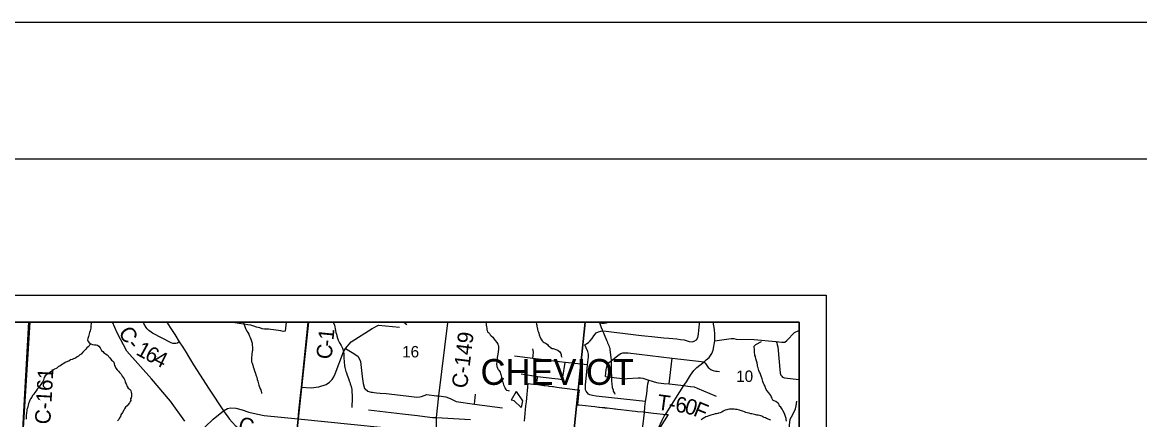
# Model space of a CAD drawing. Extents: x 0 to 34, y 0 to 22.
# Drawn here: x 6.05 to 10.15, y 20.543 to 22 of the extents above; entities that cross this region are included whole.
import ezdxf

# ---------------------------------------------------------------- set-up
doc = ezdxf.new("R2010")
doc.units = 0
for name, color, linetype in [('GM_X_City_Street', 7, 'Continuous'), ('GM_X_Corporation', 7, 'Continuous'), ('GM_X_Corporation_Text', 7, 'Continuous'), ('GM_X_County_Road', 7, 'Continuous'), ('GM_X_County_Road_Text', 7, 'Continuous'), ('GM_X_Minor_Lake', 7, 'Continuous'), ('GM_X_Minor_River', 7, 'Continuous'), ('GM_X_Rail_Line', 7, 'Continuous'), ('GM_X_Section_Text', 7, 'Continuous'), ('GM_X_Township_Road', 7, 'Continuous'), ('GM_X_Township_Road_Text', 7, 'Continuous'), ('SH_Border', 7, 'Continuous'), ('SH_Cut_Line', 7, 'Continuous'), ('SH_Data', 7, 'Continuous')]:
    doc.layers.add(name, color=color, linetype=linetype)

msp = doc.modelspace()

# ---------------------------------------------------------------- linework, layer by layer
at = {"layer": 'GM_X_City_Street'}
msp.add_line((8.3245, 20.4975), (8.3324, 20.5696), dxfattribs=at)
at = {"layer": 'GM_X_Corporation'}
for points in [[(8.9, 14.3814), (8.9, 20.9), (2.1, 20.9)], [(8.9, 17.1766), (8.9, 20.9), (4.0645, 20.9), (4.0111, 20.3696), (4.0006, 20.2658), (3.9936, 20.1954), (3.918, 19.4442), (3.8667, 18.9339), (3.8234, 18.553), (3.8126, 18.3974), (3.8023, 18.3182), (3.7454, 17.7286)], [(7.8922, 20.5373), (7.8936, 20.5515), (7.895, 20.5656), (7.8965, 20.5797), (7.8979, 20.5938), (7.8993, 20.608), (7.9007, 20.6221), (7.9023, 20.6381), (7.9033, 20.6476), (7.9049, 20.6636), (7.9061, 20.6757), (7.9146, 20.6746), (7.9149, 20.6746), (7.9324, 20.6724), (7.9418, 20.6712), (7.9632, 20.6685), (7.9681, 20.6679), (7.9794, 20.6664), (7.9822, 20.6661), (7.9955, 20.6643), (7.9973, 20.6641), (7.9992, 20.6639), (8.0117, 20.6622), (8.0286, 20.6601), (8.0301, 20.6599), (8.0593, 20.6561), (8.0765, 20.6538), (8.0767, 20.6538), (8.0923, 20.6518), (8.0926, 20.6518), (8.091, 20.6367), (8.0896, 20.6228), (8.0871, 20.5977), (8.0929, 20.597), (8.1169, 20.5944), (8.137, 20.5922), (8.1512, 20.5907), (8.1652, 20.589), (8.1679, 20.5887), (8.1773, 20.5877), (8.1856, 20.5868), (8.1868, 20.5866), (8.1962, 20.5856), (8.2059, 20.5845), (8.215, 20.5835), (8.2245, 20.5825), (8.2262, 20.5823), (8.2338, 20.5815), (8.2466, 20.5801), (8.2669, 20.5779), (8.2872, 20.5756), (8.2997, 20.5742), (8.3075, 20.5733), (8.3279, 20.5712), (8.3373, 20.5702), (8.3656, 20.5672), (8.4137, 20.562), (8.4199, 20.5613), (8.3907, 20.515)]]:
    msp.add_lwpolyline(points, dxfattribs=at)
for points in [[(6.077, 20.9), (5.0731, 20.9), (5.0456, 20.6041), (6.0521, 20.4929)], [(7.0997, 20.9), (6.077, 20.9), (6.0521, 20.4929), (7.0465, 20.3953)], [(8.1157, 20.9), (7.0997, 20.9), (7.0465, 20.3953), (8.0517, 20.2839)], [(8.9, 20.1965), (8.9, 20.9), (8.1157, 20.9), (8.0517, 20.2839)]]:
    msp.add_lwpolyline(points, close=True, dxfattribs=at)
at = {"layer": 'GM_X_County_Road'}
msp.add_line((7.0645, 20.5751), (7.0717, 20.643), dxfattribs=at)
for points in [[(6.0357, 20.3327), (6.0589, 20.3625), (6.0642, 20.3768), (6.0699, 20.4348), (6.0514, 20.507), (6.0739, 20.9)], [(6.6257, 20.828), (6.6192, 20.8239), (6.6133, 20.822), (6.6074, 20.8216), (6.602, 20.8224), (6.5954, 20.825), (6.5275, 20.8599), (6.5219, 20.8635), (6.5138, 20.8692), (6.5074, 20.8765), (6.5043, 20.8807), (6.4958, 20.8952), (6.4931, 20.9)], [(6.5797, 20.9), (6.5922, 20.8807), (6.609, 20.8555), (6.6257, 20.828), (6.6385, 20.8086), (6.6511, 20.7887), (6.6599, 20.7739), (6.6778, 20.7443), (6.7353, 20.6548), (6.7877, 20.5749), (6.8101, 20.5442), (6.8193, 20.533), (6.8328, 20.5185), (6.8419, 20.5096), (6.8623, 20.4912), (6.8749, 20.4813), (6.8851, 20.4742), (6.902, 20.4629), (6.9135, 20.4559), (6.9278, 20.4482), (6.9415, 20.4415), (6.989, 20.4219), (7.0504, 20.3965)], [(7.0717, 20.643), (7.0737, 20.6624), (7.099, 20.9)], [(7.5701, 20.4942), (7.5701, 20.5502), (7.5787, 20.6296), (7.6113, 20.8976), (7.6116, 20.9)], [(8.4122, 20.5655), (8.4775, 20.6676), (8.4871, 20.6816), (8.5023, 20.7057), (8.5143, 20.7232), (8.5254, 20.7338), (8.5521, 20.755), (8.5598, 20.7625), (8.5701, 20.7713), (8.5796, 20.7859), (8.5846, 20.7982), (8.5904, 20.8323), (8.5915, 20.856), (8.5892, 20.874), (8.5848, 20.9)], [(8.5904, 20.8323), (8.6504, 20.8401), (8.6603, 20.8399), (8.6689, 20.8381), (8.7354, 20.8374), (8.8148, 20.8292), (8.818, 20.824), (8.8202, 20.8175), (8.8217, 20.8096), (8.8313, 20.7127), (8.8333, 20.706), (8.8363, 20.7017), (8.8398, 20.6986), (8.847, 20.6963), (8.9, 20.6906)], [(6.7877, 20.5749), (6.803, 20.5835), (6.8139, 20.5861), (6.8329, 20.5848), (6.857, 20.5786), (6.8813, 20.5698), (6.9073, 20.564), (6.9367, 20.5585), (7.0614, 20.546), (7.5701, 20.4942), (7.7383, 20.4795), (7.8165, 20.4727), (7.8632, 20.4681), (7.8783, 20.4665)], [(7.0504, 20.3965), (7.0614, 20.546), (7.0645, 20.5751)], [(8.3489, 20.3815), (8.3492, 20.3828), (8.3647, 20.4587), (8.3698, 20.4768), (8.3757, 20.4915), (8.3789, 20.4993), (8.3845, 20.5117), (8.3976, 20.5409), (8.4056, 20.5553), (8.4122, 20.5655)]]:
    msp.add_lwpolyline(points, dxfattribs=at)
at = {"layer": 'GM_X_Minor_Lake'}
for points in [[(7.8623, 20.6457), (7.8855, 20.6121), (7.8808, 20.5872), (7.8551, 20.6117), (7.8441, 20.6142)], [(7.8623, 20.6457), (7.8441, 20.6142)]]:
    msp.add_lwpolyline(points, dxfattribs=at)
at = {"layer": 'GM_X_Minor_River'}
msp.add_line((7.4498, 20.9), (7.4609, 20.8916), dxfattribs=at)
for points in [[(6.3032, 20.9), (6.3019, 20.8953), (6.3013, 20.8884), (6.3015, 20.8831), (6.3013, 20.8786), (6.3004, 20.874), (6.2983, 20.8684), (6.2958, 20.862), (6.2949, 20.8575), (6.2932, 20.8526), (6.2919, 20.8477), (6.2902, 20.841), (6.2892, 20.836), (6.2913, 20.8291), (6.296, 20.8233), (6.3012, 20.8208), (6.3072, 20.8183), (6.3148, 20.8177), (6.3209, 20.8171), (6.3261, 20.8158), (6.3309, 20.8122), (6.3353, 20.8067), (6.3378, 20.8009), (6.3399, 20.7963), (6.3447, 20.7923), (6.3494, 20.7872), (6.355, 20.7844), (6.361, 20.78), (6.3705, 20.7698), (6.3767, 20.7616), (6.3811, 20.7588), (6.3851, 20.7533), (6.3868, 20.7472), (6.3881, 20.7418), (6.3899, 20.7372), (6.3927, 20.7318), (6.3978, 20.7251), (6.4022, 20.7204), (6.4062, 20.7157), (6.4121, 20.7094), (6.4164, 20.7024), (6.4229, 20.6927), (6.4254, 20.6881), (6.4274, 20.6804), (6.431, 20.6746), (6.4344, 20.6638), (6.4376, 20.6584), (6.445, 20.6532), (6.4475, 20.6485), (6.4485, 20.6439), (6.4502, 20.6378), (6.4504, 20.6332), (6.4503, 20.6287), (6.4493, 20.6234), (6.4469, 20.6189), (6.4479, 20.6136), (6.445, 20.6091), (6.4434, 20.6042), (6.4382, 20.5987), (6.4339, 20.5939), (6.4284, 20.5884)], [(6.8604, 20.9), (6.8623, 20.8953), (6.8647, 20.8876), (6.8689, 20.8775), (6.8739, 20.8675), (6.8775, 20.862), (6.8803, 20.8566), (6.8839, 20.8493), (6.886, 20.8439), (6.8877, 20.8381), (6.8901, 20.8312), (6.8925, 20.8235), (6.8934, 20.817), (6.8942, 20.8071), (6.8944, 20.8026), (6.8942, 20.7969), (6.8933, 20.7923), (6.8923, 20.7844), (6.8913, 20.7776), (6.8903, 20.7727), (6.8902, 20.7681), (6.8912, 20.7544), (6.8926, 20.7494), (6.8954, 20.7432), (6.8971, 20.7371), (6.8995, 20.7306), (6.9019, 20.7217), (6.9047, 20.7163), (6.9081, 20.7037), (6.9102, 20.6986), (6.9118, 20.6898), (6.9135, 20.6845), (6.9179, 20.6687), (6.922, 20.6564), (6.9245, 20.6518), (6.9268, 20.6411), (6.9278, 20.6385)], [(7.1914, 20.9), (7.1919, 20.8983), (7.1947, 20.8898), (7.1964, 20.8829), (7.1976, 20.8757), (7.1989, 20.8699), (7.2006, 20.863), (7.2023, 20.8569), (7.2039, 20.85), (7.2063, 20.8419), (7.2087, 20.8346), (7.2109, 20.83), (7.2137, 20.8242), (7.2194, 20.8149), (7.2227, 20.8094), (7.2248, 20.8048), (7.2272, 20.7975), (7.2285, 20.7917), (7.2294, 20.783), (7.2295, 20.7754), (7.2297, 20.77), (7.2303, 20.7548), (7.2317, 20.7403), (7.2337, 20.7342), (7.2366, 20.7193), (7.2395, 20.7146), (7.2419, 20.7054), (7.2447, 20.7004), (7.2464, 20.6935), (7.2491, 20.6854), (7.2513, 20.6804), (7.2533, 20.6738), (7.2564, 20.6642), (7.2583, 20.6531), (7.2589, 20.6482), (7.2594, 20.6421), (7.2595, 20.6341), (7.2599, 20.6223), (7.26, 20.6139), (7.2594, 20.5965), (7.2585, 20.5879)], [(7.751, 20.9), (7.751, 20.8994), (7.7516, 20.894), (7.7519, 20.8891), (7.7529, 20.8837), (7.7539, 20.878), (7.7545, 20.8726), (7.7551, 20.8695), (7.7569, 20.8649), (7.761, 20.8621), (7.7636, 20.8586), (7.7669, 20.854), (7.7698, 20.8505), (7.7762, 20.845), (7.7787, 20.8418), (7.7817, 20.838), (7.785, 20.8329), (7.7909, 20.8263), (7.7941, 20.8201), (7.7959, 20.817), (7.7969, 20.8113), (7.7967, 20.8017), (7.7943, 20.7832), (7.7933, 20.7763), (7.7924, 20.7706), (7.7917, 20.7589), (7.7908, 20.7524), (7.7902, 20.7471), (7.7911, 20.7383), (7.7918, 20.7349), (7.7929, 20.7314), (7.7954, 20.7271), (7.7984, 20.724), (7.8006, 20.7205), (7.8027, 20.7167), (7.8045, 20.712), (7.8056, 20.709), (7.8066, 20.704), (7.8079, 20.6986), (7.8093, 20.691), (7.8103, 20.6879), (7.8117, 20.6833), (7.8124, 20.6798), (7.8138, 20.6752), (7.8159, 20.6702), (7.8177, 20.6656), (7.8202, 20.6613), (7.822, 20.6571), (7.8235, 20.654), (7.8264, 20.6513), (7.8328, 20.6492), (7.8359, 20.6487)], [(7.9349, 20.9), (7.9354, 20.898), (7.9364, 20.893), (7.9375, 20.8892), (7.9381, 20.885), (7.9388, 20.8819), (7.9404, 20.8731), (7.9418, 20.8689), (7.9436, 20.8639), (7.9446, 20.8597), (7.9468, 20.8539), (7.9478, 20.8508), (7.9489, 20.8474), (7.9521, 20.8397), (7.9543, 20.8354), (7.9568, 20.8323), (7.9609, 20.8284), (7.965, 20.8264), (7.9721, 20.822), (7.9766, 20.8184), (7.9799, 20.8153), (7.9855, 20.8102), (7.9885, 20.8078), (7.9937, 20.8042), (7.9979, 20.8034), (8.0017, 20.8025), (8.0073, 20.8), (8.0111, 20.7988), (8.0144, 20.7972), (8.0219, 20.7916), (8.0259, 20.7854), (8.0273, 20.7812), (8.0276, 20.7766), (8.0293, 20.7716)], [(8.1633, 20.9), (8.1682, 20.8987), (8.1712, 20.8975), (8.1761, 20.8966), (8.1795, 20.8965), (8.1845, 20.8968), (8.1894, 20.8974), (8.1929, 20.8984), (8.1963, 20.8995), (8.1976, 20.9)], [(8.1674, 20.8989), (8.1748, 20.8776), (8.177, 20.8745), (8.1777, 20.8711), (8.1824, 20.8618), (8.1852, 20.8556), (8.1877, 20.8491), (8.1909, 20.841), (8.1934, 20.8348), (8.1956, 20.829), (8.1977, 20.8244), (8.1991, 20.8202), (8.2016, 20.8148), (8.2034, 20.8102), (8.2052, 20.8048), (8.2061, 20.7987), (8.2074, 20.7906), (8.2087, 20.7799), (8.2092, 20.7704), (8.2101, 20.7609), (8.2102, 20.751), (8.2107, 20.7407), (8.2108, 20.7327), (8.211, 20.7266), (8.2109, 20.7212), (8.2111, 20.7132), (8.2116, 20.706), (8.2119, 20.701), (8.2123, 20.6881), (8.2121, 20.6812), (8.2127, 20.6763), (8.2126, 20.6724), (8.2139, 20.6637), (8.2146, 20.6606), (8.2174, 20.6517), (8.2184, 20.6475), (8.2224, 20.6398), (8.2242, 20.6359)], [(8.8245, 20.6016), (8.8204, 20.6048), (8.8144, 20.6099), (8.8084, 20.612), (8.8035, 20.6148), (8.801, 20.6194), (8.8004, 20.6236), (8.7982, 20.6275), (8.796, 20.6318), (8.7887, 20.6415), (8.7835, 20.6489), (8.7799, 20.6539), (8.777, 20.6593), (8.7752, 20.6651), (8.772, 20.6709), (8.7688, 20.6786), (8.767, 20.6828), (8.7659, 20.6871), (8.7646, 20.692), (8.7614, 20.7017), (8.76, 20.7063), (8.7568, 20.7132), (8.7553, 20.7171), (8.7528, 20.7232), (8.7507, 20.7275), (8.7497, 20.7328), (8.749, 20.7359), (8.748, 20.7397), (8.7473, 20.7428), (8.7464, 20.7508), (8.7435, 20.7589), (8.7418, 20.7662), (8.7398, 20.7742), (8.7384, 20.7777), (8.7377, 20.7834), (8.7371, 20.788), (8.7368, 20.7918), (8.7362, 20.7979), (8.736, 20.8029), (8.7357, 20.8075), (8.7355, 20.8124), (8.741, 20.818), (8.7618, 20.8296)], [(6.3005, 20.8212), (6.2914, 20.8101), (6.2859, 20.8058), (6.2823, 20.8009), (6.278, 20.7961), (6.2721, 20.7903), (6.265, 20.7829), (6.2604, 20.7804), (6.256, 20.776), (6.2514, 20.7727), (6.2452, 20.7688), (6.2371, 20.7653), (6.2325, 20.7639), (6.2267, 20.7618), (6.2201, 20.7579), (6.2155, 20.7561), (6.2074, 20.7522), (6.2023, 20.7486), (6.1969, 20.7458), (6.1919, 20.7429), (6.1872, 20.7392), (6.1818, 20.7372), (6.1759, 20.7317), (6.1647, 20.7263), (6.16, 20.7223), (6.1546, 20.7183), (6.1491, 20.7151), (6.1433, 20.7115), (6.1382, 20.7067), (6.1332, 20.7031), (6.1299, 20.6975), (6.1283, 20.693), (6.127, 20.6881), (6.1245, 20.6821), (6.1213, 20.6773), (6.118, 20.6713), (6.1137, 20.6669), (6.1104, 20.661), (6.1041, 20.6543), (6.1009, 20.6491), (6.0958, 20.6421), (6.0914, 20.6362), (6.087, 20.6314), (6.0846, 20.6257), (6.0798, 20.6187), (6.0769, 20.6138), (6.0748, 20.6067), (6.0727, 20.6018), (6.0714, 20.5962), (6.0697, 20.5913), (6.0683, 20.5849), (6.0667, 20.5804), (6.0661, 20.5758), (6.065, 20.566), (6.064, 20.5592), (6.0637, 20.5493), (6.0632, 20.5448)], [(6.4284, 20.5884), (6.424, 20.5825), (6.4219, 20.5772), (6.4171, 20.5694), (6.4115, 20.5605), (6.4094, 20.5548), (6.4065, 20.5489), (6.4033, 20.5433), (6.3989, 20.5381)], [(8.8543, 20.5368), (8.8533, 20.5433), (8.8523, 20.5475), (8.8492, 20.5579), (8.8467, 20.5652), (8.8405, 20.5761), (8.8376, 20.5815), (8.8329, 20.5885), (8.8288, 20.5928), (8.827, 20.5966), (8.8245, 20.6016)], [(8.7959, 20.5415), (8.7872, 20.544), (8.7842, 20.5453), (8.7808, 20.5469), (8.777, 20.5493), (8.7725, 20.5513), (8.7673, 20.5534), (8.7639, 20.555), (8.7598, 20.5566), (8.7552, 20.5575), (8.7503, 20.5588), (8.7446, 20.5597), (8.7416, 20.5605), (8.7367, 20.5618), (8.7314, 20.5624), (8.7265, 20.5636), (8.7227, 20.5645), (8.7171, 20.5666), (8.7099, 20.5679), (8.7053, 20.5696), (8.6993, 20.572), (8.6933, 20.5737), (8.6891, 20.575), (8.6854, 20.5766), (8.6812, 20.5782), (8.6725, 20.5796), (8.6672, 20.5801), (8.6615, 20.5811), (8.6532, 20.5817), (8.6482, 20.5814), (8.6444, 20.5808), (8.6383, 20.5798), (8.6345, 20.5788), (8.6295, 20.577), (8.6218, 20.5734), (8.6164, 20.5701), (8.6106, 20.5676), (8.6049, 20.5663), (8.6018, 20.5656), (8.5976, 20.5646), (8.5926, 20.5636), (8.5861, 20.5618), (8.5815, 20.5608), (8.5758, 20.5587), (8.5693, 20.5574), (8.5623, 20.5541), (8.5581, 20.5531), (8.5542, 20.5506), (8.5481, 20.5469), (8.5442, 20.544), (8.5411, 20.5422)]]:
    msp.add_lwpolyline(points, dxfattribs=at)
at = {"layer": 'GM_X_Rail_Line'}
msp.add_lwpolyline([(6.6457, 20.5375), (6.5931, 20.6104), (6.5238, 20.6921), (6.4336, 20.7945), (6.3973, 20.8617), (6.38, 20.9)], dxfattribs=at)
at = {"layer": 'GM_X_Township_Road'}
for p, q in [((7.6113, 20.8976), (7.5882, 20.9)), ((8.4229, 20.6741), (8.4344, 20.7687)), ((7.9386, 20.6829), (7.9401, 20.7012)), ((7.7091, 20.5999), (7.713, 20.6363)), ((8.3364, 20.6096), (8.166, 20.6282)), ((8.3324, 20.5696), (8.3344, 20.5896))]:
    msp.add_line(p, q, dxfattribs=at)
for points in [[(7.0181, 20.9), (7.0145, 20.8678), (7.0073, 20.8664), (6.9979, 20.8684), (6.9535, 20.8742), (6.9385, 20.8751), (6.9298, 20.8763), (6.9212, 20.879), (6.9095, 20.8817), (6.8996, 20.8856), (6.8888, 20.8889), (6.8771, 20.8907), (6.8615, 20.8928), (6.813, 20.9)], [(7.0737, 20.6624), (7.1098, 20.6596), (7.1383, 20.6636), (7.1641, 20.672), (7.1764, 20.6798), (7.1872, 20.6906), (7.1923, 20.7002), (7.1979, 20.7113), (7.2287, 20.791), (7.2361, 20.8038), (7.257, 20.8279), (7.3338, 20.8777), (7.3572, 20.8897), (7.4342, 20.8824)], [(8.3214, 20.8519), (8.3344, 20.8506), (8.3592, 20.8478), (8.3816, 20.8455), (8.4036, 20.8434), (8.4217, 20.8419), (8.4516, 20.8388), (8.4646, 20.8373), (8.4788, 20.8352), (8.4972, 20.8291), (8.508, 20.8283), (8.5155, 20.8301), (8.5232, 20.835), (8.5289, 20.8437), (8.5312, 20.8566), (8.5322, 20.8712), (8.5335, 20.8822), (8.5342, 20.8938), (8.5353, 20.9)], [(8.8148, 20.8292), (8.8372, 20.827), (8.8479, 20.8275), (8.8558, 20.8335), (8.8837, 20.8622), (8.8987, 20.8702), (8.9, 20.8706)], [(8.1139, 20.8171), (8.1212, 20.8222), (8.1274, 20.826), (8.1328, 20.8309), (8.141, 20.841), (8.1467, 20.8504), (8.1521, 20.8569), (8.1561, 20.8609), (8.1637, 20.8648), (8.1729, 20.8673), (8.1824, 20.8682), (8.2915, 20.8553), (8.3103, 20.853), (8.3214, 20.8519)], [(7.2361, 20.8038), (7.266, 20.7859), (7.2816, 20.7742), (7.2909, 20.7563), (7.2963, 20.7008), (7.2999, 20.6753), (7.3059, 20.6573), (7.3082, 20.6554)], [(7.9232, 20.7668), (7.9247, 20.7776), (7.9252, 20.7901), (7.9227, 20.803)], [(8.166, 20.6282), (8.156, 20.6292), (8.1425, 20.6309), (8.1323, 20.6337), (8.1275, 20.6368), (8.1219, 20.642), (8.1191, 20.6469), (8.1169, 20.6517), (8.1161, 20.6585), (8.1166, 20.6694), (8.1238, 20.7433), (8.1272, 20.7732), (8.1269, 20.7833), (8.1245, 20.7927), (8.1192, 20.8065), (8.1139, 20.8171)], [(7.9728, 20.7607), (7.9232, 20.7668), (7.8564, 20.776)], [(7.8798, 20.7108), (7.9401, 20.7012), (8.0039, 20.6943), (8.0157, 20.692), (8.0229, 20.691), (8.0316, 20.6899), (8.0326, 20.6982), (8.0416, 20.7519)], [(8.1238, 20.7433), (8.0416, 20.7519), (7.9797, 20.7598), (7.9728, 20.7607)], [(8.1894, 20.7005), (8.1927, 20.7263), (8.196, 20.7412), (8.1997, 20.7474), (8.2045, 20.7533), (8.2402, 20.7817), (8.2464, 20.7853), (8.2531, 20.7876), (8.2601, 20.7884), (8.273, 20.7873), (8.4344, 20.7687), (8.5521, 20.755)], [(8.5521, 20.755), (8.5546, 20.7515), (8.557, 20.7483), (8.5592, 20.7449), (8.5617, 20.7411), (8.5639, 20.7377), (8.567, 20.7344), (8.5696, 20.7319), (8.5721, 20.7297), (8.576, 20.727), (8.5816, 20.7241), (8.5854, 20.7227), (8.5899, 20.7218), (8.5942, 20.7211), (8.6001, 20.7205), (8.6084, 20.7199)], [(8.1894, 20.7005), (8.2513, 20.6933), (8.2585, 20.6931), (8.2692, 20.6939), (8.3102, 20.6962), (8.3177, 20.696), (8.3262, 20.6949), (8.3372, 20.6919), (8.3491, 20.6878), (8.3767, 20.6796), (8.3847, 20.678), (8.4038, 20.6759), (8.4229, 20.6741), (8.4775, 20.6676)], [(8.3344, 20.5896), (8.3364, 20.6096), (8.3409, 20.6372), (8.3434, 20.6638), (8.3454, 20.6746), (8.3491, 20.6878)], [(8.4775, 20.6676), (8.4922, 20.6659), (8.5023, 20.6646), (8.5149, 20.6631), (8.5256, 20.6587), (8.596, 20.6292)], [(7.3082, 20.6554), (7.3176, 20.6477), (7.3246, 20.6447), (7.3293, 20.6435), (7.3342, 20.6432), (7.3408, 20.6429), (7.3495, 20.6416), (7.3629, 20.6405), (7.3847, 20.6383), (7.4582, 20.6301), (7.4979, 20.6254), (7.5081, 20.6259), (7.5148, 20.6274), (7.5339, 20.6356), (7.5691, 20.6305), (7.5787, 20.6296), (7.6044, 20.6271), (7.6199, 20.6205), (7.6367, 20.6115), (7.642, 20.6095), (7.7091, 20.5999), (7.8123, 20.5867)], [(8.8614, 20.4866), (8.8663, 20.5339), (8.8678, 20.5447), (8.872, 20.5537), (8.8812, 20.5693), (8.8871, 20.5819), (8.8897, 20.5935), (8.8915, 20.6107)], [(6.6912, 20.4885), (6.7499, 20.5442), (6.7877, 20.5749)], [(7.32, 20.5789), (7.4442, 20.5645), (7.5001, 20.5581), (7.5269, 20.554), (7.5549, 20.551), (7.5701, 20.5502), (7.694, 20.5434)]]:
    msp.add_lwpolyline(points, dxfattribs=at)
at = {"layer": 'SH_Border'}
msp.add_lwpolyline([(1.5, 21.5), (33.5, 21.5), (33.5, 0.5), (1.5, 0.5)], close=True, dxfattribs=at)
at = {"layer": 'SH_Cut_Line'}
msp.add_lwpolyline([(0, 0), (34, 0), (34, 22), (0, 22)], close=True, dxfattribs=at)
at = {"layer": 'SH_Data'}
for p, q in [((2, 21), (9, 21)), ((9, 21), (9, 14)), ((2.1, 20.9), (8.9, 20.9)), ((8.9, 20.9), (8.9, 14.1))]:
    msp.add_line(p, q, dxfattribs=at)

# ---------------------------------------------------------------- texts
at = {"layer": 'GM_X_Corporation_Text'}
msp.add_text('CHEVIOT', height=0.0947, rotation=0, dxfattribs=at).set_placement((7.7313, 20.6704))
at = {"layer": 'GM_X_County_Road_Text'}
for s, height, rotation, p in [('C', 0.0568, 300.6958, (6.4006, 20.8639)), ('1', 0.0568, 84.3611, (7.1914, 20.8324)), ('-', 0.0568, 84.1355, (7.189, 20.809)), ('C-149', 0.05682, 83.0806, (7.6815, 20.6558)), ('-', 0.0568, 310.9021, (6.4309, 20.8148)), ('1', 0.0568, 331.2505, (6.4632, 20.7834)), ('6', 0.0568, 332.5993, (6.4952, 20.7659)), ('4', 0.0568, 333.6344, (6.5272, 20.7492)), ('C', 0.0568, 84.0873, (7.1842, 20.7625)), ('C-161', 0.05682, 86.6984, (6.1521, 20.5245)), ('C', 0.0568, 343.9721, (6.8375, 20.5019))]:
    msp.add_text(s, height=height, rotation=rotation, dxfattribs=at).set_placement(p)
at = {"layer": 'GM_X_Section_Text'}
for s, p in [('16', (7.4435, 20.7711)), ('10', (8.6693, 20.6811))]:
    msp.add_text(s, height=0.04186, rotation=0, dxfattribs=at).set_placement(p)
at = {"layer": 'GM_X_Township_Road_Text'}
for s, rotation, p in [('T', 352.2754, (8.3769, 20.58)), ('6', 354.3088, (8.4443, 20.5709)), ('-', 352.3952, (8.4191, 20.5743)), ('0', 344.1668, (8.4765, 20.568)), ('F', 337.7808, (8.5086, 20.559))]:
    msp.add_text(s, height=0.0568, rotation=rotation, dxfattribs=at).set_placement(p)

doc.saveas('drawing.dxf')
